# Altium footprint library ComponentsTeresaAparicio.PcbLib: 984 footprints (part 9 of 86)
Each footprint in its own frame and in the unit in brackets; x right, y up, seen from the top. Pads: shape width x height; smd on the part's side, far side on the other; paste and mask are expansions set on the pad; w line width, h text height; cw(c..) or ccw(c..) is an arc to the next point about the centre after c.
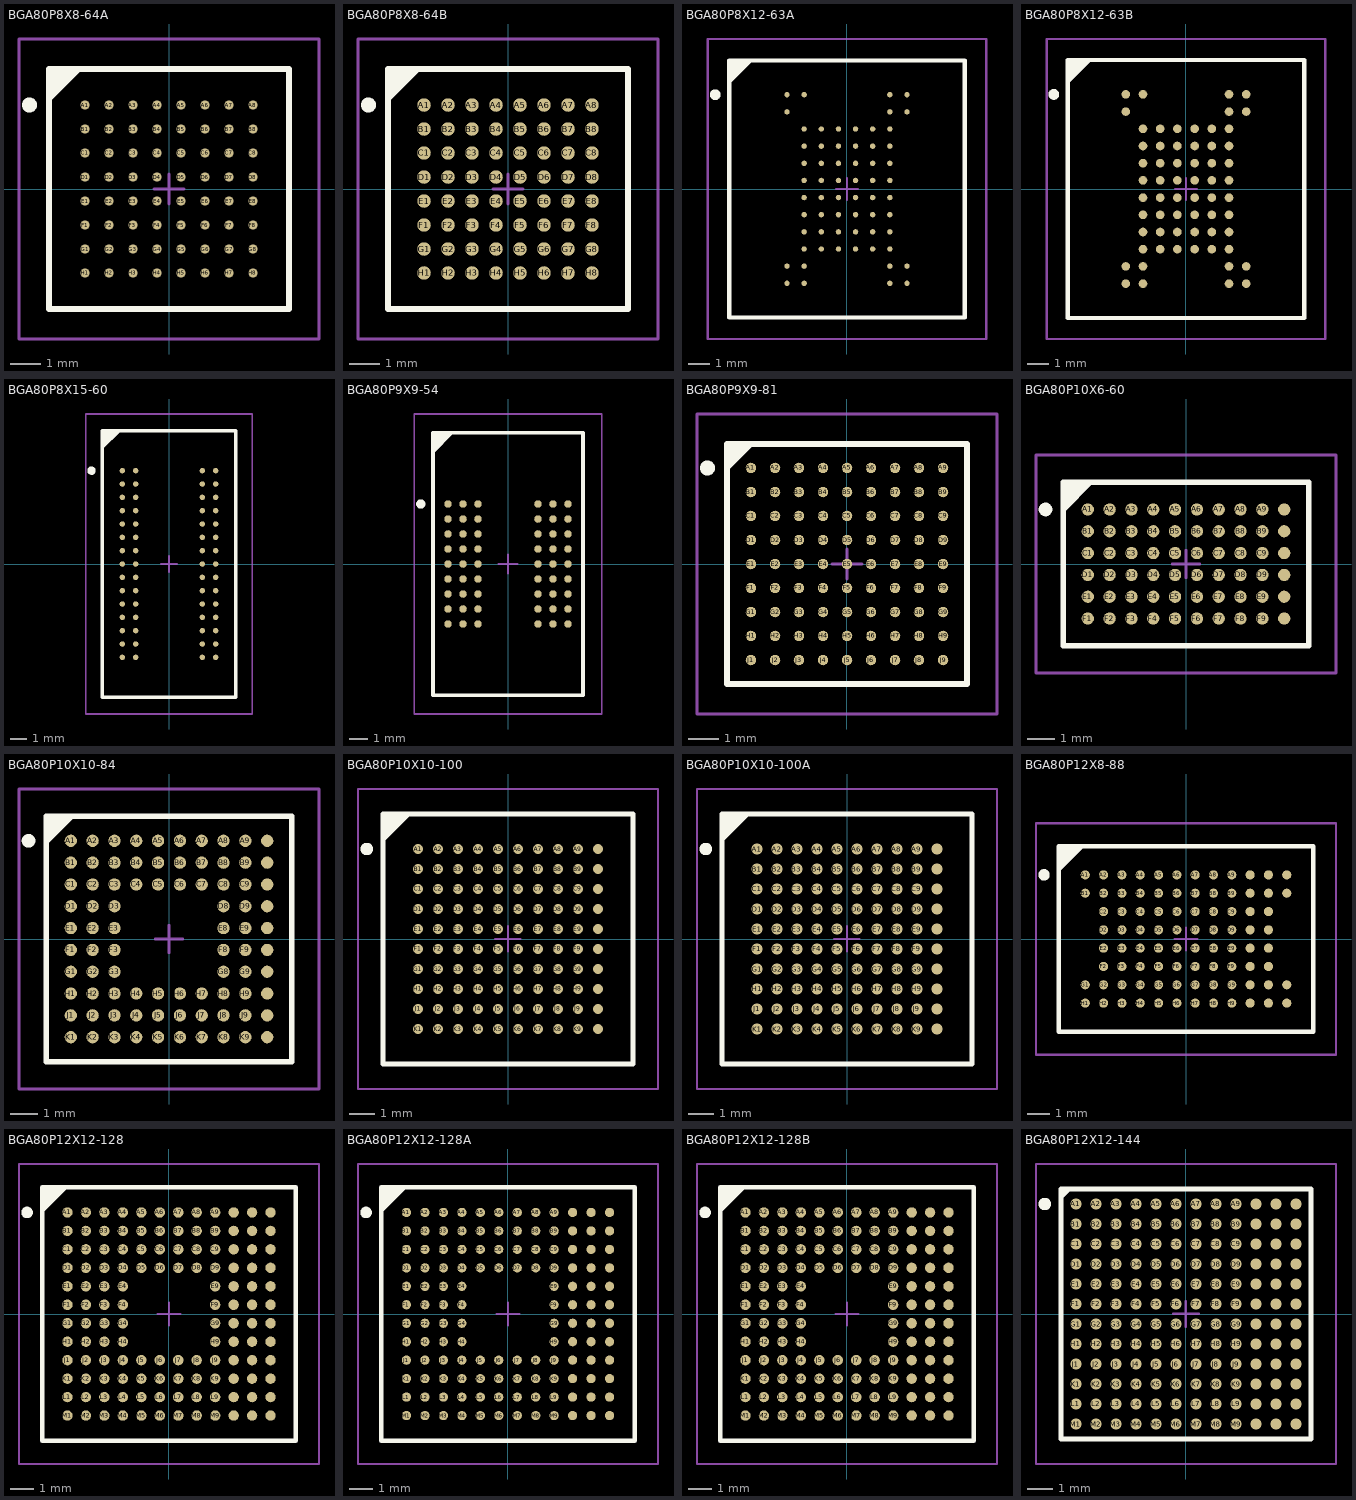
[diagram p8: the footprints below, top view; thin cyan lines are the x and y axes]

## BGA80P8X8-64A [mm] "BGA, 64-Leads, Body 8x8mm, Pitch 0.8mm"
height 1.1
pads (64):
  round 0.3 smd: A1(-2.8,2.8) A2(-2,2.8) A3(-1.2,2.8) A4(-0.4,2.8) A5(0.4,2.8) A6(1.2,2.8) A7(2,2.8) A8(2.8,2.8) B1(-2.8,2) B2(-2,2) B3(-1.2,2) B4(-0.4,2) B5(0.4,2) B6(1.2,2) B7(2,2) B8(2.8,2) C1(-2.8,1.2) C2(-2,1.2) C3(-1.2,1.2) C4(-0.4,1.2) C5(0.4,1.2) C6(1.2,1.2) C7(2,1.2) C8(2.8,1.2) D1(-2.8,0.4) D2(-2,0.4) D3(-1.2,0.4) D4(-0.4,0.4) D5(0.4,0.4) D6(1.2,0.4) D7(2,0.4) D8(2.8,0.4) E1(-2.8,-0.4) E2(-2,-0.4) E3(-1.2,-0.4) E4(-0.4,-0.4) E5(0.4,-0.4) E6(1.2,-0.4) E7(2,-0.4) E8(2.8,-0.4) F1(-2.8,-1.2) F2(-2,-1.2) F3(-1.2,-1.2) F4(-0.4,-1.2) F5(0.4,-1.2) F6(1.2,-1.2) F7(2,-1.2) F8(2.8,-1.2) G1(-2.8,-2) G2(-2,-2) G3(-1.2,-2) G4(-0.4,-2) G5(0.4,-2) G6(1.2,-2) G7(2,-2) G8(2.8,-2) H1(-2.8,-2.8) H2(-2,-2.8) H3(-1.2,-2.8) H4(-0.4,-2.8) H5(0.4,-2.8) H6(1.2,-2.8) H7(2,-2.8) H8(2.8,-2.8)
Top Overlay:
  circle w0.25: c-4.65,2.8 r0.125
  region: -3,4 -4,3 -4,4
  lines w0.2: -4,3 -3,4 ; -4,-4 4,-4 4,4 -4,4 -4,-4
Mechanical 13:
  lines w0.1: -4,-4 4,-4 4,4 -4,4 -4,-4
Mechanical 15:
  lines w0.1: -0.5,0 0.5,0 ; 0,-0.5 0,0.5 ; -5,-5 5,-5 5,5 -5,5 -5,-5
3D body: height 1.1, standoff 0, extent -4,-4 4,4

## BGA80P8X8-64B [mm] "BGA, 64-Leads, Body 8x8mm, Pitch 0.8mm"
height 1.7
pads (64):
  round 0.45 smd: A1(-2.8,2.8) A2(-2,2.8) A3(-1.2,2.8) A4(-0.4,2.8) A5(0.4,2.8) A6(1.2,2.8) A7(2,2.8) A8(2.8,2.8) B1(-2.8,2) B2(-2,2) B3(-1.2,2) B4(-0.4,2) B5(0.4,2) B6(1.2,2) B7(2,2) B8(2.8,2) C1(-2.8,1.2) C2(-2,1.2) C3(-1.2,1.2) C4(-0.4,1.2) C5(0.4,1.2) C6(1.2,1.2) C7(2,1.2) C8(2.8,1.2) D1(-2.8,0.4) D2(-2,0.4) D3(-1.2,0.4) D4(-0.4,0.4) D5(0.4,0.4) D6(1.2,0.4) D7(2,0.4) D8(2.8,0.4) E1(-2.8,-0.4) E2(-2,-0.4) E3(-1.2,-0.4) E4(-0.4,-0.4) E5(0.4,-0.4) E6(1.2,-0.4) E7(2,-0.4) E8(2.8,-0.4) F1(-2.8,-1.2) F2(-2,-1.2) F3(-1.2,-1.2) F4(-0.4,-1.2) F5(0.4,-1.2) F6(1.2,-1.2) F7(2,-1.2) F8(2.8,-1.2) G1(-2.8,-2) G2(-2,-2) G3(-1.2,-2) G4(-0.4,-2) G5(0.4,-2) G6(1.2,-2) G7(2,-2) G8(2.8,-2) H1(-2.8,-2.8) H2(-2,-2.8) H3(-1.2,-2.8) H4(-0.4,-2.8) H5(0.4,-2.8) H6(1.2,-2.8) H7(2,-2.8) H8(2.8,-2.8)
Top Overlay:
  circle w0.25: c-4.65,2.8 r0.125
  region: -3,4 -4,3 -4,4
  lines w0.2: -4,3 -3,4 ; -4,-4 4,-4 4,4 -4,4 -4,-4
Mechanical 13:
  lines w0.1: -4,-4 4,-4 4,4 -4,4 -4,-4
Mechanical 15:
  lines w0.1: -0.5,0 0.5,0 ; 0,-0.5 0,0.5 ; -5,-5 5,-5 5,5 -5,5 -5,-5
3D body: height 1.1, standoff 0, extent -4,-4 4,4

## BGA80P8X12-63A [mm] "63-Ball Fine Pitch Ball Grid Array Rectangular 0.8 mm Pitch"
height 1.2
pads (63):
  round 0.25 smd: A1(-2.8,4.4) A2(-2,4.4) A7(2,4.4) A8(2.8,4.4) B1(-2.8,3.6) B7(2,3.6) B8(2.8,3.6) C2(-2,2.8) C3(-1.2,2.8) C4(-0.4,2.8) C5(0.4,2.8) C6(1.2,2.8) C7(2,2.8) D2(-2,2) D3(-1.2,2) D4(-0.4,2) D5(0.4,2) D6(1.2,2) D7(2,2) E2(-2,1.2) E3(-1.2,1.2) E4(-0.4,1.2) E5(0.4,1.2) E6(1.2,1.2) E7(2,1.2) F2(-2,0.4) F3(-1.2,0.4) F4(-0.4,0.4) F5(0.4,0.4) F6(1.2,0.4) F7(2,0.4) G2(-2,-0.4) G3(-1.2,-0.4) G4(-0.4,-0.4) G5(0.4,-0.4) G6(1.2,-0.4) G7(2,-0.4) H2(-2,-1.2) H3(-1.2,-1.2) H4(-0.4,-1.2) H5(0.4,-1.2) H6(1.2,-1.2) H7(2,-1.2) J2(-2,-2) J3(-1.2,-2) J4(-0.4,-2) J5(0.4,-2) J6(1.2,-2) J7(2,-2) K2(-2,-2.8) K3(-1.2,-2.8) K4(-0.4,-2.8) K5(0.4,-2.8) K6(1.2,-2.8) K7(2,-2.8) L1(-2.8,-3.6) L2(-2,-3.6) L7(2,-3.6) L8(2.8,-3.6) M1(-2.8,-4.4) M2(-2,-4.4) M7(2,-4.4) M8(2.8,-4.4)
Top Overlay:
  circle w0.25: c-6.15,4.4 r0.125
  region: -4.5,6 -5.5,5 -5.5,6
  lines w0.2: -5.5,5 -4.5,6 ; -5.5,-6 -5.5,6 5.5,6 5.5,-6 -5.5,-6
Mechanical 13:
  lines w0.1: -5.5,-6 -5.5,6 5.5,6 5.5,-6 -5.5,-6
Mechanical 15:
  lines w0.1: -0.5,0 0.5,0 ; 0,-0.5 0,0.5 ; -6.5,-7 -6.5,7 6.5,7 6.5,-7 -6.5,-7
3D body: height 1.2, standoff 0, extent -5.5,-6 5.5,6

## BGA80P8X12-63B [mm] "63-Ball Fine Pitch Ball Grid Array Rectangular 0.8 mm Pitch"
height 1.7
pads (63):
  round 0.4 smd: A1(-2.8,4.4) A2(-2,4.4) A7(2,4.4) A8(2.8,4.4) B1(-2.8,3.6) B7(2,3.6) B8(2.8,3.6) C2(-2,2.8) C3(-1.2,2.8) C4(-0.4,2.8) C5(0.4,2.8) C6(1.2,2.8) C7(2,2.8) D2(-2,2) D3(-1.2,2) D4(-0.4,2) D5(0.4,2) D6(1.2,2) D7(2,2) E2(-2,1.2) E3(-1.2,1.2) E4(-0.4,1.2) E5(0.4,1.2) E6(1.2,1.2) E7(2,1.2) F2(-2,0.4) F3(-1.2,0.4) F4(-0.4,0.4) F5(0.4,0.4) F6(1.2,0.4) F7(2,0.4) G2(-2,-0.4) G3(-1.2,-0.4) G4(-0.4,-0.4) G5(0.4,-0.4) G6(1.2,-0.4) G7(2,-0.4) H2(-2,-1.2) H3(-1.2,-1.2) H4(-0.4,-1.2) H5(0.4,-1.2) H6(1.2,-1.2) H7(2,-1.2) J2(-2,-2) J3(-1.2,-2) J4(-0.4,-2) J5(0.4,-2) J6(1.2,-2) J7(2,-2) K2(-2,-2.8) K3(-1.2,-2.8) K4(-0.4,-2.8) K5(0.4,-2.8) K6(1.2,-2.8) K7(2,-2.8) L1(-2.8,-3.6) L2(-2,-3.6) L7(2,-3.6) L8(2.8,-3.6) M1(-2.8,-4.4) M2(-2,-4.4) M7(2,-4.4) M8(2.8,-4.4)
Top Overlay:
  circle w0.25: c-6.15,4.4 r0.125
  region: -4.5,6 -5.5,5 -5.5,6
  lines w0.2: -5.5,5 -4.5,6 ; -5.5,-6 5.5,-6 5.5,6 -5.5,6 -5.5,-6
Mechanical 13:
  lines w0.1: -5.475,-5.975 5.475,-5.975 5.475,5.975 -5.475,5.975 -5.475,-5.975
Mechanical 15:
  lines w0.1: -0.5,0 0.5,0 ; 0,-0.5 0,0.5 ; -6.475,-6.975 6.475,-6.975 6.475,6.975 -6.475,6.975 -6.475,-6.975
3D body: height 1.7, standoff 0, extent -5.475,-5.975 5.475,5.975

## BGA80P8X15-60 [mm] "BGA, 60-Leads, Body 16x8mm, Pitch 0.8mm"
height 1.2
pads (60):
  round 0.33 smd: A1(-2.8,5.6) A2(-2,5.6) A7(2,5.6) A8(2.8,5.6) B1(-2.8,4.8) B2(-2,4.8) B7(2,4.8) B8(2.8,4.8) C1(-2.8,4) C2(-2,4) C7(2,4) C8(2.8,4) D1(-2.8,3.2) D2(-2,3.2) D7(2,3.2) D8(2.8,3.2) E1(-2.8,2.4) E2(-2,2.4) E7(2,2.4) E8(2.8,2.4) F1(-2.8,1.6) F2(-2,1.6) F7(2,1.6) F8(2.8,1.6) G1(-2.8,0.8) G2(-2,0.8) G7(2,0.8) G8(2.8,0.8) H1(-2.8,0) H2(-2,0) H7(2,0) H8(2.8,0) J1(-2.8,-0.8) J2(-2,-0.8) J7(2,-0.8) J8(2.8,-0.8) K1(-2.8,-1.6) K2(-2,-1.6) K7(2,-1.6) K8(2.8,-1.6) L1(-2.8,-2.4) L2(-2,-2.4) L7(2,-2.4) L8(2.8,-2.4) M1(-2.8,-3.2) M2(-2,-3.2) M7(2,-3.2) M8(2.8,-3.2) N1(-2.8,-4) N2(-2,-4) N7(2,-4) N8(2.8,-4) P1(-2.8,-4.8) P2(-2,-4.8) P7(2,-4.8) P8(2.8,-4.8) R1(-2.8,-5.6) R2(-2,-5.6) R7(2,-5.6) R8(2.8,-5.6)
Top Overlay:
  circle w0.25: c-4.65,5.6 r0.125
  region: -3,8 -4,7 -4,8
  lines w0.2: -4,7 -3,8 ; -4,-8 -4,8 4,8 4,-8 -4,-8
Mechanical 13:
  lines w0.1: -4,-8 -4,8 4,8 4,-8 -4,-8
Mechanical 15:
  lines w0.1: -0.5,0 0.5,0 ; 0,-0.5 0,0.5 ; -5,-9 -5,9 5,9 5,-9 -5,-9
3D body: height 1.2, standoff 0, extent -4,-8 4,8

## BGA80P9X9-54 [mm] "54-Ball VFBGA, 8 x 14 mm Body, 0.8 mm Pitch (FG)"
height 1
pads (54):
  round 0.4 smd: A1(-3.2,3.2) A2(-2.4,3.2) A3(-1.6,3.2) A7(1.6,3.2) A8(2.4,3.2) A9(3.2,3.2) B1(-3.2,2.4) B2(-2.4,2.4) B3(-1.6,2.4) B7(1.6,2.4) B8(2.4,2.4) B9(3.2,2.4) C1(-3.2,1.6) C2(-2.4,1.6) C3(-1.6,1.6) C7(1.6,1.6) C8(2.4,1.6) C9(3.2,1.6) D1(-3.2,0.8) D2(-2.4,0.8) D3(-1.6,0.8) D7(1.6,0.8) D8(2.4,0.8) D9(3.2,0.8) E1(-3.2,0) E2(-2.4,0) E3(-1.6,0) E7(1.6,0) E8(2.4,0) E9(3.2,0) F1(-3.2,-0.8) F2(-2.4,-0.8) F3(-1.6,-0.8) F7(1.6,-0.8) F8(2.4,-0.8) F9(3.2,-0.8) G1(-3.2,-1.6) G2(-2.4,-1.6) G3(-1.6,-1.6) G7(1.6,-1.6) G8(2.4,-1.6) G9(3.2,-1.6) H1(-3.2,-2.4) H2(-2.4,-2.4) H3(-1.6,-2.4) H7(1.6,-2.4) H8(2.4,-2.4) H9(3.2,-2.4) J1(-3.2,-3.2) J2(-2.4,-3.2) J3(-1.6,-3.2) J7(1.6,-3.2) J8(2.4,-3.2) J9(3.2,-3.2)
Top Overlay:
  circle w0.25: c-4.65,3.2 r0.125
  region: -3,7 -4,6 -4,7
  lines w0.2: -4,6 -3,7 ; -4,-7 4,-7 4,7 -4,7 -4,-7
Mechanical 13:
  lines w0.1: -4,-7 4,-7 4,7 -4,7 -4,-7
Mechanical 15:
  lines w0.1: -0.5,0 0.5,0 ; 0,-0.5 0,0.5 ; -5,-8 5,-8 5,8 -5,8 -5,-8
3D body: height 1, standoff 0, extent -4,-7 4,7

## BGA80P9X9-81 [mm] "BGA, 81-Leads, Body 8x8mm, Pitch 0.8mm"
height 1.3
pads (81):
  round 0.35 smd: A1(-3.2,3.2) A2(-2.4,3.2) A3(-1.6,3.2) A4(-0.8,3.2) A5(0,3.2) A6(0.8,3.2) A7(1.6,3.2) A8(2.4,3.2) A9(3.2,3.2) B1(-3.2,2.4) B2(-2.4,2.4) B3(-1.6,2.4) B4(-0.8,2.4) B5(0,2.4) B6(0.8,2.4) B7(1.6,2.4) B8(2.4,2.4) B9(3.2,2.4) C1(-3.2,1.6) C2(-2.4,1.6) C3(-1.6,1.6) C4(-0.8,1.6) C5(0,1.6) C6(0.8,1.6) C7(1.6,1.6) C8(2.4,1.6) C9(3.2,1.6) D1(-3.2,0.8) D2(-2.4,0.8) D3(-1.6,0.8) D4(-0.8,0.8) D5(0,0.8) D6(0.8,0.8) D7(1.6,0.8) D8(2.4,0.8) D9(3.2,0.8) E1(-3.2,0) E2(-2.4,0) E3(-1.6,0) E4(-0.8,0) E5(0,0) E6(0.8,0) E7(1.6,0) E8(2.4,0) E9(3.2,0) F1(-3.2,-0.8) F2(-2.4,-0.8) F3(-1.6,-0.8) F4(-0.8,-0.8) F5(0,-0.8) F6(0.8,-0.8) F7(1.6,-0.8) F8(2.4,-0.8) F9(3.2,-0.8) G1(-3.2,-1.6) G2(-2.4,-1.6) G3(-1.6,-1.6) G4(-0.8,-1.6) G5(0,-1.6) G6(0.8,-1.6) G7(1.6,-1.6) G8(2.4,-1.6) G9(3.2,-1.6) H1(-3.2,-2.4) H2(-2.4,-2.4) H3(-1.6,-2.4) H4(-0.8,-2.4) H5(0,-2.4) H6(0.8,-2.4) H7(1.6,-2.4) H8(2.4,-2.4) H9(3.2,-2.4) J1(-3.2,-3.2) J2(-2.4,-3.2) J3(-1.6,-3.2) J4(-0.8,-3.2) J5(0,-3.2) J6(0.8,-3.2) J7(1.6,-3.2) J8(2.4,-3.2) J9(3.2,-3.2)
Top Overlay:
  circle w0.25: c-4.65,3.2 r0.125
  region: -3.213,4 -4,3.213 -4,4
  lines w0.2: -4,3.213 -3.213,4 ; -4,-4 -4,4 4,4 4,-4 -4,-4
Mechanical 13:
  lines w0.1: -4,-4 -4,4 4,4 4,-4 -4,-4
Mechanical 15:
  lines w0.1: -0.5,0 0.5,0 ; 0,-0.5 0,0.5 ; -5,-5 -5,5 5,5 5,-5 -5,-5
3D body: height 1.3, standoff 0, extent -4,-4 4,4

## BGA80P10X6-60 [mm] "BGA, 60-Leads, Body 6x9mm, Pitch 0.8mm"
height 1.3
pads (60):
  round 0.45 smd: A1(-3.6,2) A2(-2.8,2) A3(-2,2) A4(-1.2,2) A5(-0.4,2) A6(0.4,2) A7(1.2,2) A8(2,2) A9(2.8,2) A10(3.6,2) B1(-3.6,1.2) B2(-2.8,1.2) B3(-2,1.2) B4(-1.2,1.2) B5(-0.4,1.2) B6(0.4,1.2) B7(1.2,1.2) B8(2,1.2) B9(2.8,1.2) B10(3.6,1.2) C1(-3.6,0.4) C2(-2.8,0.4) C3(-2,0.4) C4(-1.2,0.4) C5(-0.4,0.4) C6(0.4,0.4) C7(1.2,0.4) C8(2,0.4) C9(2.8,0.4) C10(3.6,0.4) D1(-3.6,-0.4) D2(-2.8,-0.4) D3(-2,-0.4) D4(-1.2,-0.4) D5(-0.4,-0.4) D6(0.4,-0.4) D7(1.2,-0.4) D8(2,-0.4) D9(2.8,-0.4) D10(3.6,-0.4) E1(-3.6,-1.2) E2(-2.8,-1.2) E3(-2,-1.2) E4(-1.2,-1.2) E5(-0.4,-1.2) E6(0.4,-1.2) E7(1.2,-1.2) E8(2,-1.2) E9(2.8,-1.2) E10(3.6,-1.2) F1(-3.6,-2) F2(-2.8,-2) F3(-2,-2) F4(-1.2,-2) F5(-0.4,-2) F6(0.4,-2) F7(1.2,-2) F8(2,-2) F9(2.8,-2) F10(3.6,-2)
Top Overlay:
  circle w0.25: c-5.15,2 r0.125
  region: -3.5,3 -4.5,2 -4.5,3
  lines w0.2: -4.5,2 -3.5,3 ; -4.5,-3 -4.5,3 4.5,3 4.5,-3 -4.5,-3
Mechanical 13:
  lines w0.1: -4.5,-3 -4.5,3 4.5,3 4.5,-3 -4.5,-3
Mechanical 15:
  lines w0.1: -0.5,0 0.5,0 ; 0,-0.5 0,0.5 ; -5.5,-4 -5.5,4 5.5,4 5.5,-4 -5.5,-4
3D body: height 1.3, standoff 0.3, extent -4.5,-3 4.5,3

## BGA80P10X10-84 [mm] "BGA, 84-Leads, Body 9x9mm, Pitch 0.8mm"
height 1.5
pads (84):
  round 0.45 smd: A1(-3.6,3.6) A2(-2.8,3.6) A3(-2,3.6) A4(-1.2,3.6) A5(-0.4,3.6) A6(0.4,3.6) A7(1.2,3.6) A8(2,3.6) A9(2.8,3.6) A10(3.6,3.6) B1(-3.6,2.8) B2(-2.8,2.8) B3(-2,2.8) B4(-1.2,2.8) B5(-0.4,2.8) B6(0.4,2.8) B7(1.2,2.8) B8(2,2.8) B9(2.8,2.8) B10(3.6,2.8) C1(-3.6,2) C2(-2.8,2) C3(-2,2) C4(-1.2,2) C5(-0.4,2) C6(0.4,2) C7(1.2,2) C8(2,2) C9(2.8,2) C10(3.6,2) D1(-3.6,1.2) D2(-2.8,1.2) D3(-2,1.2) D8(2,1.2) D9(2.8,1.2) D10(3.6,1.2) E1(-3.6,0.4) E2(-2.8,0.4) E3(-2,0.4) E8(2,0.4) E9(2.8,0.4) E10(3.6,0.4) F1(-3.6,-0.4) F2(-2.8,-0.4) F3(-2,-0.4) F8(2,-0.4) F9(2.8,-0.4) F10(3.6,-0.4) G1(-3.6,-1.2) G2(-2.8,-1.2) G3(-2,-1.2) G8(2,-1.2) G9(2.8,-1.2) G10(3.6,-1.2) H1(-3.6,-2) H2(-2.8,-2) H3(-2,-2) H4(-1.2,-2) H5(-0.4,-2) H6(0.4,-2) H7(1.2,-2) H8(2,-2) H9(2.8,-2) H10(3.6,-2) J1(-3.6,-2.8) J2(-2.8,-2.8) J3(-2,-2.8) J4(-1.2,-2.8) J5(-0.4,-2.8) J6(0.4,-2.8) J7(1.2,-2.8) J8(2,-2.8) J9(2.8,-2.8) J10(3.6,-2.8) K1(-3.6,-3.6) K2(-2.8,-3.6) K3(-2,-3.6) K4(-1.2,-3.6) K5(-0.4,-3.6) K6(0.4,-3.6) K7(1.2,-3.6) K8(2,-3.6) K9(2.8,-3.6) K10(3.6,-3.6)
Top Overlay:
  circle w0.25: c-5.15,3.6 r0.125
  region: -3.584,4.5 -4.5,3.584 -4.5,4.5
  lines w0.2: -4.5,3.584 -3.584,4.5 ; -4.5,-4.5 -4.5,4.5 4.5,4.5 4.5,-4.5 -4.5,-4.5
Mechanical 13:
  lines w0.1: -4.5,-4.5 -4.5,4.5 4.5,4.5 4.5,-4.5 -4.5,-4.5
Mechanical 15:
  lines w0.1: -0.5,0 0.5,0 ; 0,-0.5 0,0.5 ; -5.5,-5.5 -5.5,5.5 5.5,5.5 5.5,-5.5 -5.5,-5.5
3D body: height 1.5, standoff 0.5, extent -4.5,-4.5 4.5,4.5

## BGA80P10X10-100 [mm] "BGA, 100-Leads, Body 10x10mm, Pitch 0.8mm"
height 1.5
pads (100):
  round 0.4 smd: A1(-3.6,3.6) A2(-2.8,3.6) A3(-2,3.6) A4(-1.2,3.6) A5(-0.4,3.6) A6(0.4,3.6) A7(1.2,3.6) A8(2,3.6) A9(2.8,3.6) A10(3.6,3.6) B1(-3.6,2.8) B2(-2.8,2.8) B3(-2,2.8) B4(-1.2,2.8) B5(-0.4,2.8) B6(0.4,2.8) B7(1.2,2.8) B8(2,2.8) B9(2.8,2.8) B10(3.6,2.8) C1(-3.6,2) C2(-2.8,2) C3(-2,2) C4(-1.2,2) C5(-0.4,2) C6(0.4,2) C7(1.2,2) C8(2,2) C9(2.8,2) C10(3.6,2) D1(-3.6,1.2) D2(-2.8,1.2) D3(-2,1.2) D4(-1.2,1.2) D5(-0.4,1.2) D6(0.4,1.2) D7(1.2,1.2) D8(2,1.2) D9(2.8,1.2) D10(3.6,1.2) E1(-3.6,0.4) E2(-2.8,0.4) E3(-2,0.4) E4(-1.2,0.4) E5(-0.4,0.4) E6(0.4,0.4) E7(1.2,0.4) E8(2,0.4) E9(2.8,0.4) E10(3.6,0.4) F1(-3.6,-0.4) F2(-2.8,-0.4) F3(-2,-0.4) F4(-1.2,-0.4) F5(-0.4,-0.4) F6(0.4,-0.4) F7(1.2,-0.4) F8(2,-0.4) F9(2.8,-0.4) F10(3.6,-0.4) G1(-3.6,-1.2) G2(-2.8,-1.2) G3(-2,-1.2) G4(-1.2,-1.2) G5(-0.4,-1.2) G6(0.4,-1.2) G7(1.2,-1.2) G8(2,-1.2) G9(2.8,-1.2) G10(3.6,-1.2) H1(-3.6,-2) H2(-2.8,-2) H3(-2,-2) H4(-1.2,-2) H5(-0.4,-2) H6(0.4,-2) H7(1.2,-2) H8(2,-2) H9(2.8,-2) H10(3.6,-2) J1(-3.6,-2.8) J2(-2.8,-2.8) J3(-2,-2.8) J4(-1.2,-2.8) J5(-0.4,-2.8) J6(0.4,-2.8) J7(1.2,-2.8) J8(2,-2.8) J9(2.8,-2.8) J10(3.6,-2.8) K1(-3.6,-3.6) K2(-2.8,-3.6) K3(-2,-3.6) K4(-1.2,-3.6) K5(-0.4,-3.6) K6(0.4,-3.6) K7(1.2,-3.6) K8(2,-3.6) K9(2.8,-3.6) K10(3.6,-3.6)
Top Overlay:
  circle w0.25: c-5.65,3.6 r0.125
  region: -4,5 -5,4 -5,5
  lines w0.2: -5,4 -4,5 ; -5,-5 -5,5 5,5 5,-5 -5,-5
Mechanical 13:
  lines w0.1: -5,-5 -5,5 5,5 5,-5 -5,-5
Mechanical 15:
  lines w0.1: -0.5,0 0.5,0 ; 0,-0.5 0,0.5 ; -6,-6 -6,6 6,6 6,-6 -6,-6
3D body: height 1.5, standoff 0, extent -5,-5 5,5

## BGA80P10X10-100A [mm] "BGA, 100-Leads, Body 10x10mm, Pitch 0.8mm"
height 1.7
pads (100):
  round 0.45 smd: A1(-3.6,3.6) A2(-2.8,3.6) A3(-2,3.6) A4(-1.2,3.6) A5(-0.4,3.6) A6(0.4,3.6) A7(1.2,3.6) A8(2,3.6) A9(2.8,3.6) A10(3.6,3.6) B1(-3.6,2.8) B2(-2.8,2.8) B3(-2,2.8) B4(-1.2,2.8) B5(-0.4,2.8) B6(0.4,2.8) B7(1.2,2.8) B8(2,2.8) B9(2.8,2.8) B10(3.6,2.8) C1(-3.6,2) C2(-2.8,2) C3(-2,2) C4(-1.2,2) C5(-0.4,2) C6(0.4,2) C7(1.2,2) C8(2,2) C9(2.8,2) C10(3.6,2) D1(-3.6,1.2) D2(-2.8,1.2) D3(-2,1.2) D4(-1.2,1.2) D5(-0.4,1.2) D6(0.4,1.2) D7(1.2,1.2) D8(2,1.2) D9(2.8,1.2) D10(3.6,1.2) E1(-3.6,0.4) E2(-2.8,0.4) E3(-2,0.4) E4(-1.2,0.4) E5(-0.4,0.4) E6(0.4,0.4) E7(1.2,0.4) E8(2,0.4) E9(2.8,0.4) E10(3.6,0.4) F1(-3.6,-0.4) F2(-2.8,-0.4) F3(-2,-0.4) F4(-1.2,-0.4) F5(-0.4,-0.4) F6(0.4,-0.4) F7(1.2,-0.4) F8(2,-0.4) F9(2.8,-0.4) F10(3.6,-0.4) G1(-3.6,-1.2) G2(-2.8,-1.2) G3(-2,-1.2) G4(-1.2,-1.2) G5(-0.4,-1.2) G6(0.4,-1.2) G7(1.2,-1.2) G8(2,-1.2) G9(2.8,-1.2) G10(3.6,-1.2) H1(-3.6,-2) H2(-2.8,-2) H3(-2,-2) H4(-1.2,-2) H5(-0.4,-2) H6(0.4,-2) H7(1.2,-2) H8(2,-2) H9(2.8,-2) H10(3.6,-2) J1(-3.6,-2.8) J2(-2.8,-2.8) J3(-2,-2.8) J4(-1.2,-2.8) J5(-0.4,-2.8) J6(0.4,-2.8) J7(1.2,-2.8) J8(2,-2.8) J9(2.8,-2.8) J10(3.6,-2.8) K1(-3.6,-3.6) K2(-2.8,-3.6) K3(-2,-3.6) K4(-1.2,-3.6) K5(-0.4,-3.6) K6(0.4,-3.6) K7(1.2,-3.6) K8(2,-3.6) K9(2.8,-3.6) K10(3.6,-3.6)
Top Overlay:
  circle w0.25: c-5.65,3.6 r0.125
  region: -4,5 -5,4 -5,5
  lines w0.2: -5,4 -4,5 ; -5,-5 -5,5 5,5 5,-5 -5,-5
Mechanical 13:
  lines w0.1: -5,-5 -5,5 5,5 5,-5 -5,-5
Mechanical 15:
  lines w0.1: -0.5,0 0.5,0 ; 0,-0.5 0,0.5 ; -6,-6 -6,6 6,6 6,-6 -6,-6
3D body: height 1.5, standoff 0, extent -5,-5 5,5

## BGA80P12X8-88 [mm] "BGA, 88-Leads, Body 8x11mm, Pitch 0.8mm"
height 1.4
pads (88):
  round 0.4 smd: A1(-4.4,2.8) A2(-3.6,2.8) A3(-2.8,2.8) A4(-2,2.8) A5(-1.2,2.8) A6(-0.4,2.8) A7(0.4,2.8) A8(1.2,2.8) A9(2,2.8) A10(2.8,2.8) A11(3.6,2.8) A12(4.4,2.8) B1(-4.4,2) B2(-3.6,2) B3(-2.8,2) B4(-2,2) B5(-1.2,2) B6(-0.4,2) B7(0.4,2) B8(1.2,2) B9(2,2) B10(2.8,2) B11(3.6,2) B12(4.4,2) C2(-3.6,1.2) C3(-2.8,1.2) C4(-2,1.2) C5(-1.2,1.2) C6(-0.4,1.2) C7(0.4,1.2) C8(1.2,1.2) C9(2,1.2) C10(2.8,1.2) C11(3.6,1.2) D2(-3.6,0.4) D3(-2.8,0.4) D4(-2,0.4) D5(-1.2,0.4) D6(-0.4,0.4) D7(0.4,0.4) D8(1.2,0.4) D9(2,0.4) D10(2.8,0.4) D11(3.6,0.4) E2(-3.6,-0.4) E3(-2.8,-0.4) E4(-2,-0.4) E5(-1.2,-0.4) E6(-0.4,-0.4) E7(0.4,-0.4) E8(1.2,-0.4) E9(2,-0.4) E10(2.8,-0.4) E11(3.6,-0.4) F2(-3.6,-1.2) F3(-2.8,-1.2) F4(-2,-1.2) F5(-1.2,-1.2) F6(-0.4,-1.2) F7(0.4,-1.2) F8(1.2,-1.2) F9(2,-1.2) F10(2.8,-1.2) F11(3.6,-1.2) G1(-4.4,-2) G2(-3.6,-2) G3(-2.8,-2) G4(-2,-2) G5(-1.2,-2) G6(-0.4,-2) G7(0.4,-2) G8(1.2,-2) G9(2,-2) G10(2.8,-2) G11(3.6,-2) G12(4.4,-2) H1(-4.4,-2.8) H2(-3.6,-2.8) H3(-2.8,-2.8) H4(-2,-2.8) H5(-1.2,-2.8) H6(-0.4,-2.8) H7(0.4,-2.8) H8(1.2,-2.8) H9(2,-2.8) H10(2.8,-2.8) H11(3.6,-2.8) H12(4.4,-2.8)
Top Overlay:
  circle w0.25: c-6.2,2.8 r0.125
  region: -4.55,4.05 -5.55,3.05 -5.55,4.05
  lines w0.2: -5.55,3.05 -4.55,4.05 ; -5.55,-4.05 -5.55,4.05 5.55,4.05 5.55,-4.05 -5.55,-4.05
Mechanical 13:
  lines w0.1: -5.55,-4.05 -5.55,4.05 5.55,4.05 5.55,-4.05 -5.55,-4.05
Mechanical 15:
  lines w0.1: -0.5,0 0.5,0 ; 0,-0.5 0,0.5 ; -6.55,-5.05 -6.55,5.05 6.55,5.05 6.55,-5.05 -6.55,-5.05
3D body: height 1.4, standoff 0, extent -5.55,-4.05 5.55,4.05

## BGA80P12X12-128 [mm] "BGA, 128-Leads, Body 11x11mm, Pitch 0.8mm"
height 1.5
pads (128):
  round 0.45 smd: A1(-4.4,4.4) A2(-3.6,4.4) A3(-2.8,4.4) A4(-2,4.4) A5(-1.2,4.4) A6(-0.4,4.4) A7(0.4,4.4) A8(1.2,4.4) A9(2,4.4) A10(2.8,4.4) A11(3.6,4.4) A12(4.4,4.4) B1(-4.4,3.6) B2(-3.6,3.6) B3(-2.8,3.6) B4(-2,3.6) B5(-1.2,3.6) B6(-0.4,3.6) B7(0.4,3.6) B8(1.2,3.6) B9(2,3.6) B10(2.8,3.6) B11(3.6,3.6) B12(4.4,3.6) C1(-4.4,2.8) C2(-3.6,2.8) C3(-2.8,2.8) C4(-2,2.8) C5(-1.2,2.8) C6(-0.4,2.8) C7(0.4,2.8) C8(1.2,2.8) C9(2,2.8) C10(2.8,2.8) C11(3.6,2.8) C12(4.4,2.8) D1(-4.4,2) D2(-3.6,2) D3(-2.8,2) D4(-2,2) D5(-1.2,2) D6(-0.4,2) D7(0.4,2) D8(1.2,2) D9(2,2) D10(2.8,2) D11(3.6,2) D12(4.4,2) E1(-4.4,1.2) E2(-3.6,1.2) E3(-2.8,1.2) E4(-2,1.2) E9(2,1.2) E10(2.8,1.2) E11(3.6,1.2) E12(4.4,1.2) F1(-4.4,0.4) F2(-3.6,0.4) F3(-2.8,0.4) F4(-2,0.4) F9(2,0.4) F10(2.8,0.4) F11(3.6,0.4) F12(4.4,0.4) G1(-4.4,-0.4) G2(-3.6,-0.4) G3(-2.8,-0.4) G4(-2,-0.4) G9(2,-0.4) G10(2.8,-0.4) G11(3.6,-0.4) G12(4.4,-0.4) H1(-4.4,-1.2) H2(-3.6,-1.2) H3(-2.8,-1.2) H4(-2,-1.2) H9(2,-1.2) H10(2.8,-1.2) H11(3.6,-1.2) H12(4.4,-1.2) J1(-4.4,-2) J2(-3.6,-2) J3(-2.8,-2) J4(-2,-2) J5(-1.2,-2) J6(-0.4,-2) J7(0.4,-2) J8(1.2,-2) J9(2,-2) J10(2.8,-2) J11(3.6,-2) J12(4.4,-2) K1(-4.4,-2.8) K2(-3.6,-2.8) K3(-2.8,-2.8) K4(-2,-2.8) K5(-1.2,-2.8) K6(-0.4,-2.8) K7(0.4,-2.8) K8(1.2,-2.8) K9(2,-2.8) K10(2.8,-2.8) K11(3.6,-2.8) K12(4.4,-2.8) L1(-4.4,-3.6) L2(-3.6,-3.6) L3(-2.8,-3.6) L4(-2,-3.6) L5(-1.2,-3.6) L6(-0.4,-3.6) L7(0.4,-3.6) L8(1.2,-3.6) L9(2,-3.6) L10(2.8,-3.6) L11(3.6,-3.6) L12(4.4,-3.6) M1(-4.4,-4.4) M2(-3.6,-4.4) M3(-2.8,-4.4) M4(-2,-4.4) M5(-1.2,-4.4) M6(-0.4,-4.4) M7(0.4,-4.4) M8(1.2,-4.4) M9(2,-4.4) M10(2.8,-4.4) M11(3.6,-4.4) M12(4.4,-4.4)
Top Overlay:
  circle w0.25: c-6.15,4.4 r0.125
  region: -4.5,5.5 -5.5,4.5 -5.5,5.5
  lines w0.2: -5.5,4.5 -4.5,5.5 ; -5.5,-5.5 -5.5,5.5 5.5,5.5 5.5,-5.5 -5.5,-5.5
Mechanical 13:
  lines w0.1: -5.5,-5.5 -5.5,5.5 5.5,5.5 5.5,-5.5 -5.5,-5.5
Mechanical 15:
  lines w0.1: -0.5,0 0.5,0 ; 0,-0.5 0,0.5 ; -6.5,-6.5 -6.5,6.5 6.5,6.5 6.5,-6.5 -6.5,-6.5
3D body: height 1.5, standoff 0, extent -5.5,-5.5 5.5,5.5

## BGA80P12X12-128A [mm] "BGA, 128-Leads, Body 11x11mm, Pitch 0.8mm"
height 1.5
pads (128):
  round 0.4 smd: A1(-4.4,4.4) A2(-3.6,4.4) A3(-2.8,4.4) A4(-2,4.4) A5(-1.2,4.4) A6(-0.4,4.4) A7(0.4,4.4) A8(1.2,4.4) A9(2,4.4) A10(2.8,4.4) A11(3.6,4.4) A12(4.4,4.4) B1(-4.4,3.6) B2(-3.6,3.6) B3(-2.8,3.6) B4(-2,3.6) B5(-1.2,3.6) B6(-0.4,3.6) B7(0.4,3.6) B8(1.2,3.6) B9(2,3.6) B10(2.8,3.6) B11(3.6,3.6) B12(4.4,3.6) C1(-4.4,2.8) C2(-3.6,2.8) C3(-2.8,2.8) C4(-2,2.8) C5(-1.2,2.8) C6(-0.4,2.8) C7(0.4,2.8) C8(1.2,2.8) C9(2,2.8) C10(2.8,2.8) C11(3.6,2.8) C12(4.4,2.8) D1(-4.4,2) D2(-3.6,2) D3(-2.8,2) D4(-2,2) D5(-1.2,2) D6(-0.4,2) D7(0.4,2) D8(1.2,2) D9(2,2) D10(2.8,2) D11(3.6,2) D12(4.4,2) E1(-4.4,1.2) E2(-3.6,1.2) E3(-2.8,1.2) E4(-2,1.2) E9(2,1.2) E10(2.8,1.2) E11(3.6,1.2) E12(4.4,1.2) F1(-4.4,0.4) F2(-3.6,0.4) F3(-2.8,0.4) F4(-2,0.4) F9(2,0.4) F10(2.8,0.4) F11(3.6,0.4) F12(4.4,0.4) G1(-4.4,-0.4) G2(-3.6,-0.4) G3(-2.8,-0.4) G4(-2,-0.4) G9(2,-0.4) G10(2.8,-0.4) G11(3.6,-0.4) G12(4.4,-0.4) H1(-4.4,-1.2) H2(-3.6,-1.2) H3(-2.8,-1.2) H4(-2,-1.2) H9(2,-1.2) H10(2.8,-1.2) H11(3.6,-1.2) H12(4.4,-1.2) J1(-4.4,-2) J2(-3.6,-2) J3(-2.8,-2) J4(-2,-2) J5(-1.2,-2) J6(-0.4,-2) J7(0.4,-2) J8(1.2,-2) J9(2,-2) J10(2.8,-2) J11(3.6,-2) J12(4.4,-2) K1(-4.4,-2.8) K2(-3.6,-2.8) K3(-2.8,-2.8) K4(-2,-2.8) K5(-1.2,-2.8) K6(-0.4,-2.8) K7(0.4,-2.8) K8(1.2,-2.8) K9(2,-2.8) K10(2.8,-2.8) K11(3.6,-2.8) K12(4.4,-2.8) L1(-4.4,-3.6) L2(-3.6,-3.6) L3(-2.8,-3.6) L4(-2,-3.6) L5(-1.2,-3.6) L6(-0.4,-3.6) L7(0.4,-3.6) L8(1.2,-3.6) L9(2,-3.6) L10(2.8,-3.6) L11(3.6,-3.6) L12(4.4,-3.6) M1(-4.4,-4.4) M2(-3.6,-4.4) M3(-2.8,-4.4) M4(-2,-4.4) M5(-1.2,-4.4) M6(-0.4,-4.4) M7(0.4,-4.4) M8(1.2,-4.4) M9(2,-4.4) M10(2.8,-4.4) M11(3.6,-4.4) M12(4.4,-4.4)
Top Overlay:
  circle w0.25: c-6.15,4.4 r0.125
  region: -4.5,5.5 -5.5,4.5 -5.5,5.5
  lines w0.2: -5.5,4.5 -4.5,5.5 ; -5.5,-5.5 5.5,-5.5 5.5,5.5 -5.5,5.5 -5.5,-5.5
Mechanical 13:
  lines w0.1: -5.5,-5.5 5.5,-5.5 5.5,5.5 -5.5,5.5 -5.5,-5.5
Mechanical 15:
  lines w0.1: -0.5,0 0.5,0 ; 0,-0.5 0,0.5 ; -6.5,-6.5 6.5,-6.5 6.5,6.5 -6.5,6.5 -6.5,-6.5
3D body: height 1.5, standoff 0, extent -5.5,-5.5 5.5,5.5

## BGA80P12X12-128B [mm] "BGA, 128-Leads, Body 11x11mm, Pitch 0.8mm"
height 1.4
pads (128):
  round 0.45 smd: A1(-4.4,4.4) A2(-3.6,4.4) A3(-2.8,4.4) A4(-2,4.4) A5(-1.2,4.4) A6(-0.4,4.4) A7(0.4,4.4) A8(1.2,4.4) A9(2,4.4) A10(2.8,4.4) A11(3.6,4.4) A12(4.4,4.4) B1(-4.4,3.6) B2(-3.6,3.6) B3(-2.8,3.6) B4(-2,3.6) B5(-1.2,3.6) B6(-0.4,3.6) B7(0.4,3.6) B8(1.2,3.6) B9(2,3.6) B10(2.8,3.6) B11(3.6,3.6) B12(4.4,3.6) C1(-4.4,2.8) C2(-3.6,2.8) C3(-2.8,2.8) C4(-2,2.8) C5(-1.2,2.8) C6(-0.4,2.8) C7(0.4,2.8) C8(1.2,2.8) C9(2,2.8) C10(2.8,2.8) C11(3.6,2.8) C12(4.4,2.8) D1(-4.4,2) D2(-3.6,2) D3(-2.8,2) D4(-2,2) D5(-1.2,2) D6(-0.4,2) D7(0.4,2) D8(1.2,2) D9(2,2) D10(2.8,2) D11(3.6,2) D12(4.4,2) E1(-4.4,1.2) E2(-3.6,1.2) E3(-2.8,1.2) E4(-2,1.2) E9(2,1.2) E10(2.8,1.2) E11(3.6,1.2) E12(4.4,1.2) F1(-4.4,0.4) F2(-3.6,0.4) F3(-2.8,0.4) F4(-2,0.4) F9(2,0.4) F10(2.8,0.4) F11(3.6,0.4) F12(4.4,0.4) G1(-4.4,-0.4) G2(-3.6,-0.4) G3(-2.8,-0.4) G4(-2,-0.4) G9(2,-0.4) G10(2.8,-0.4) G11(3.6,-0.4) G12(4.4,-0.4) H1(-4.4,-1.2) H2(-3.6,-1.2) H3(-2.8,-1.2) H4(-2,-1.2) H9(2,-1.2) H10(2.8,-1.2) H11(3.6,-1.2) H12(4.4,-1.2) J1(-4.4,-2) J2(-3.6,-2) J3(-2.8,-2) J4(-2,-2) J5(-1.2,-2) J6(-0.4,-2) J7(0.4,-2) J8(1.2,-2) J9(2,-2) J10(2.8,-2) J11(3.6,-2) J12(4.4,-2) K1(-4.4,-2.8) K2(-3.6,-2.8) K3(-2.8,-2.8) K4(-2,-2.8) K5(-1.2,-2.8) K6(-0.4,-2.8) K7(0.4,-2.8) K8(1.2,-2.8) K9(2,-2.8) K10(2.8,-2.8) K11(3.6,-2.8) K12(4.4,-2.8) L1(-4.4,-3.6) L2(-3.6,-3.6) L3(-2.8,-3.6) L4(-2,-3.6) L5(-1.2,-3.6) L6(-0.4,-3.6) L7(0.4,-3.6) L8(1.2,-3.6) L9(2,-3.6) L10(2.8,-3.6) L11(3.6,-3.6) L12(4.4,-3.6) M1(-4.4,-4.4) M2(-3.6,-4.4) M3(-2.8,-4.4) M4(-2,-4.4) M5(-1.2,-4.4) M6(-0.4,-4.4) M7(0.4,-4.4) M8(1.2,-4.4) M9(2,-4.4) M10(2.8,-4.4) M11(3.6,-4.4) M12(4.4,-4.4)
Top Overlay:
  circle w0.25: c-6.15,4.4 r0.125
  region: -4.5,5.5 -5.5,4.5 -5.5,5.5
  lines w0.2: -5.5,4.5 -4.5,5.5 ; -5.5,-5.5 5.5,-5.5 5.5,5.5 -5.5,5.5 -5.5,-5.5
Mechanical 13:
  lines w0.1: -5.5,-5.5 5.5,-5.5 5.5,5.5 -5.5,5.5 -5.5,-5.5
Mechanical 15:
  lines w0.1: -0.5,0 0.5,0 ; 0,-0.5 0,0.5 ; -6.5,-6.5 6.5,-6.5 6.5,6.5 -6.5,6.5 -6.5,-6.5
3D body: height 1.4, standoff 0, extent -5.5,-5.5 5.5,5.5

## BGA80P12X12-144 [mm] "BGA, 144-Leads, Body 10x10mm, Pitch 0.8mm"
height 1.4
pads (144):
  round 0.45 smd: A1(-4.4,4.4) A2(-3.6,4.4) A3(-2.8,4.4) A4(-2,4.4) A5(-1.2,4.4) A6(-0.4,4.4) A7(0.4,4.4) A8(1.2,4.4) A9(2,4.4) A10(2.8,4.4) A11(3.6,4.4) A12(4.4,4.4) B1(-4.4,3.6) B2(-3.6,3.6) B3(-2.8,3.6) B4(-2,3.6) B5(-1.2,3.6) B6(-0.4,3.6) B7(0.4,3.6) B8(1.2,3.6) B9(2,3.6) B10(2.8,3.6) B11(3.6,3.6) B12(4.4,3.6) C1(-4.4,2.8) C2(-3.6,2.8) C3(-2.8,2.8) C4(-2,2.8) C5(-1.2,2.8) C6(-0.4,2.8) C7(0.4,2.8) C8(1.2,2.8) C9(2,2.8) C10(2.8,2.8) C11(3.6,2.8) C12(4.4,2.8) D1(-4.4,2) D2(-3.6,2) D3(-2.8,2) D4(-2,2) D5(-1.2,2) D6(-0.4,2) D7(0.4,2) D8(1.2,2) D9(2,2) D10(2.8,2) D11(3.6,2) D12(4.4,2) E1(-4.4,1.2) E2(-3.6,1.2) E3(-2.8,1.2) E4(-2,1.2) E5(-1.2,1.2) E6(-0.4,1.2) E7(0.4,1.2) E8(1.2,1.2) E9(2,1.2) E10(2.8,1.2) E11(3.6,1.2) E12(4.4,1.2) F1(-4.4,0.4) F2(-3.6,0.4) F3(-2.8,0.4) F4(-2,0.4) F5(-1.2,0.4) F6(-0.4,0.4) F7(0.4,0.4) F8(1.2,0.4) F9(2,0.4) F10(2.8,0.4) F11(3.6,0.4) F12(4.4,0.4) G1(-4.4,-0.4) G2(-3.6,-0.4) G3(-2.8,-0.4) G4(-2,-0.4) G5(-1.2,-0.4) G6(-0.4,-0.4) G7(0.4,-0.4) G8(1.2,-0.4) G9(2,-0.4) G10(2.8,-0.4) G11(3.6,-0.4) G12(4.4,-0.4) H1(-4.4,-1.2) H2(-3.6,-1.2) H3(-2.8,-1.2) H4(-2,-1.2) H5(-1.2,-1.2) H6(-0.4,-1.2) H7(0.4,-1.2) H8(1.2,-1.2) H9(2,-1.2) H10(2.8,-1.2) H11(3.6,-1.2) H12(4.4,-1.2) J1(-4.4,-2) J2(-3.6,-2) J3(-2.8,-2) J4(-2,-2) J5(-1.2,-2) J6(-0.4,-2) J7(0.4,-2) J8(1.2,-2) J9(2,-2) J10(2.8,-2) J11(3.6,-2) J12(4.4,-2) K1(-4.4,-2.8) K2(-3.6,-2.8) K3(-2.8,-2.8) K4(-2,-2.8) K5(-1.2,-2.8) K6(-0.4,-2.8) K7(0.4,-2.8) K8(1.2,-2.8) K9(2,-2.8) K10(2.8,-2.8) K11(3.6,-2.8) K12(4.4,-2.8) L1(-4.4,-3.6) L2(-3.6,-3.6) L3(-2.8,-3.6) L4(-2,-3.6) L5(-1.2,-3.6) L6(-0.4,-3.6) L7(0.4,-3.6) L8(1.2,-3.6) L9(2,-3.6) L10(2.8,-3.6) L11(3.6,-3.6) L12(4.4,-3.6) M1(-4.4,-4.4) M2(-3.6,-4.4) M3(-2.8,-4.4) M4(-2,-4.4) M5(-1.2,-4.4) M6(-0.4,-4.4) M7(0.4,-4.4) M8(1.2,-4.4) M9(2,-4.4) M10(2.8,-4.4) M11(3.6,-4.4) M12(4.4,-4.4)
Top Overlay:
  circle w0.25: c-5.65,4.4 r0.125
  region: -4.684,5 -5,4.684 -5,5
  lines w0.2: -5,4.684 -4.684,5 ; -5,-5 -5,5 5,5 5,-5 -5,-5
Mechanical 13:
  lines w0.1: -5,-5 -5,5 5,5 5,-5 -5,-5
Mechanical 15:
  lines w0.1: -0.5,0 0.5,0 ; 0,-0.5 0,0.5 ; -6,-6 -6,6 6,6 6,-6 -6,-6
3D body: height 1.4, standoff 0, extent -5,-5 5,5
